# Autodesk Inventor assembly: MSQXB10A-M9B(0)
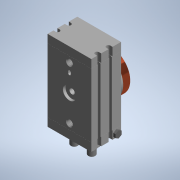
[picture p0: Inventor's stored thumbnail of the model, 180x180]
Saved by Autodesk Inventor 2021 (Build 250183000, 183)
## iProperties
Category: PARTsolutions
Part Number: MSQXB10A-M9B(0)
Catalog Web Link: www.cadenas.de
Description: MSQX-Low-Speed Rotary Table Rack & Pinion Style
Document SubType Name: Assembly
Designer: partserver
Mass: 168.018 g
Surface Area: 337.625 cm^2
Volume: 168.018 cm^3
Density: 1 g/cm^3
PSOL_IDENT_0: {$CADENAS_DATA\23d-libs\smc_jp\actuator\rotary_actuator\msqx\msqx_asmtab.prj},218 {VTYP=3D},{STYP=AS
PSOL_IDENT_1: STAB},{NB=MSQXB10A-M9B(0)},{LINA=MSQXB10A-M9B},{NN=MSQX},{DATE=09.12.2020 02:49:37},{GEOMDATE=09.03.
PSOL_IDENT_2: 2020 10:24:15},{VERSION=},{LINEID=160},{WBVAR=THREAD1,AUTOSW,LEAD,NUMBER,OMSC,THREAD},{WBNUMERIC=}
PSOL_IDENT_3: {NB=MSQXB10A-M9B(0)},{LINA=MSQXB10A-M9B},{KT=DUMMY},{ORDER=MSQXB10A-M9B},{SIZE=10},{THREAD1=},{AUTOS
PSOL_IDENT_4: W=-M9B},{LEAD=},{LEADX= '','(-) 0.5 m' , 'M','(M) 1 m' , 'L','(L) 3 m' , 'Z','(Z) 5 m' },{NUMBER=},{
PSOL_IDENT_5: SWSIGNX= '','(-) 2 pcs' , 'S','(S) 1 pc' },{PORTX= '', '(-) M5' },{OMSC=},{THREAD=0},{NENN=MSQXB10},
PSOL_IDENT_6: {MODEL=MSQXB10A-M9B},{X=},{TIF=1},{AA=55.4},{A=50},{AU=8.6},{AV=20.0},{AW=15.5},{AX=12},{AY=4},{BA=9
PSOL_IDENT_7: .5},{BB=34.5},{BC=27.8},{BD=60},{BE=27},{CA=4.5},{CB=28.5},{D=45h9},{D1=45},{DD=46h9},{DD1=46},{DE=2
PSOL_IDENT_8: 0H9},{DE1=20},{DF=6},{DG=15H9},{DG1=15},{FA=8.0},{FB=4.0},{FC=3.0},{FD=4.5},{H=13},{J=6.8},{JA=11.0}
PSOL_IDENT_9: ,{JB=6.5},{JC=M8x1.25},{JC1=8},{JCP=1.25},{JD=12},{JJ=M5x0.8},{JJ1=5},{JJP=0.80},{JU=M8x1},{JU1=8},{
PSOL_IDENT_10: JUP=1.0},{P=M5x0.8},{P1=5.000},{PP=0.8},{Q=34},{S=92},{SD=9.0},{SE=13},{SF=45},{SU=17.7},{UU=47},{WA=
PSOL_IDENT_11: 15.0},{WB=3H9},{WB1=3},{WC=3.5},{WD=M5x0.8},{WD1=5},{WDP=0.80},{WE=8.0},{WF=32},{XA=27},{XB=3H9},{XB
PSOL_IDENT_12: 1=3},{XC=3.5},{YA=19},{YB=3H9},{YB1=3},{YC=3.5},{F1=6.917},{F2=5},{Y1=8},{Y2=12},{H1=5.000},{H2=5.00
PSOL_IDENT_13: 0},{SWA=61},{SWB=43},{PD=0.3},{EA=47.1},{EB=44.3},{EC=33.5},{ED=14.0},{EE=91.4},{EF=80},{GA=20},{GB=
PSOL_IDENT_14: 15.6},{GC=11},{GD=7.5},{GE=45.2},{K=M8x1},{NA=10.0},{MB=5.5},{NC=12.5},{ND=4},{PPATH=assembly/msqx_a
PSOL_IDENT_15: smsbl.prj}
NB: MSQXB10A-M9B(0)
NN: MSQX
NT: Low-Speed Rotary Table Rack & Pinion Style
NBSYN: $ORDER.($THREAD.)
LINA: MSQXB10A-M9B
CATALOG: SMC (JP
ROWDESC: MSQXB10
SIZE: 10
THREAD1: (-) M5
AUTOSW: M9B Solid state-General-Grommet-Indicator light:Yes-2 wire-In line
LEAD: (-) 0.5 m
NUMBER: (-) 2 pcs
OMSC: (-) Without order
THREAD: on
ARTICLENO: MSQXB10A-M9B(0)
BOMINFO: MSQXB10A-M9B
CREATOR: CADENAS GmbH
Title: MSQXB10A-M9B
Author: Cadenas PARTsolutions
Comments: Low-Speed Rotary Table Rack & Pinion Style
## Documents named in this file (5)
- D:\01 Paralaia\Grupos de Traballo\GT Maquetas\CAD 3D\E_AlimentaciónV1\SMC_JP_MSQXB10AM9B0\MSQXB10A-M9B(0).iam
- D:\01 Paralaia\Grupos de Traballo\GT Maquetas\CAD 3D\E_AlimentaciónV1\SMC_JP_MSQXB10AM9B0\MSQX10(0)_BODY.ipt
- D:\01 Paralaia\Grupos de Traballo\GT Maquetas\CAD 3D\E_AlimentaciónV1\SMC_JP_MSQXB10AM9B0\MSQX10(0)_Table.ipt
- D:\01 Paralaia\Grupos de Traballo\GT Maquetas\CAD 3D\E_AlimentaciónV1\SMC_JP_MSQXB10AM9B0\MSQX_M-5P.ipt
- D:\01 Paralaia\Grupos de Traballo\GT Maquetas\CAD 3D\E_AlimentaciónV1\SMC_JP_MSQXB10AM9B0\D-M9B_MSQX.ipt
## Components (6 placed, 4 different names)
1. MSQX10(0)_BODY:1
2. MSQX10(0)_Table:1 — Insertar:1
3. MSQX_M-5P:1
4. MSQX_M-5P:2
5. D-M9B_MSQX:1
6. D-M9B_MSQX:2
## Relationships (1: Insert 1)
- Insertar:1: MSQX10(0)_Table:1
